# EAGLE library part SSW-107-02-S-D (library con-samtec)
THROUGH-HOLE .025" SQ POST SOCKET Source: Samtec SSW.pdf
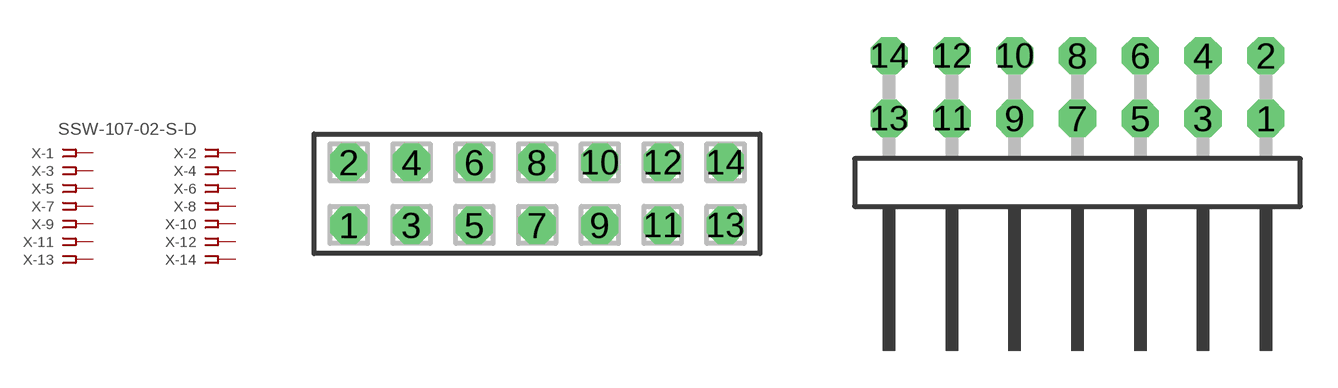
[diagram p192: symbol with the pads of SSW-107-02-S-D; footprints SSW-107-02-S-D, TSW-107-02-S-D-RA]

Designator prefix X; gates -1=FPINV -2=FPIN -3=FPIN -4=FPIN -5=FPIN -6=FPIN -7=FPIN -8=FPIN -9=FPIN -10=FPIN -11=FPIN -12=FPIN -13=FPIN -14=FPIN

## SSW-107-02-S-D (MPN: SSW-107-02-S-D; OC_FARNELL: unknown; OC_NEWARK: 11P9431)  [SSW-107-02-S-D]
1  -1:1  pas
2  -2:1  pas
3  -3:1  pas
4  -4:1  pas
5  -5:1  pas
6  -6:1  pas
7  -7:1  pas
8  -8:1  pas
9  -9:1  pas
10  -10:1  pas
11  -11:1  pas
12  -12:1  pas
13  -13:1  pas
14  -14:1  pas

## SSW-107-02-S-D-RA (MPN: SSW-107-02-S-D-RA; OC_FARNELL: unknown; OC_NEWARK: 11P9432)  [TSW-107-02-S-D-RA]
Pads as for SSW-107-02-S-D

## Footprint SSW-107-02-S-D (pad centres in mm)
THROUGH-HOLE .025" SQ POST SOCKET Source: Samtec SSW.pdf
drill 1 pad 1.5 octagon: 1 -7.62,-1.27; 2 -7.62,1.27; 3 -5.08,-1.27; 4 -5.08,1.27; 5 -2.54,-1.27; 6 -2.54,1.27; 7 0,-1.27; 8 0,1.27; 9 2.54,-1.27; 10 2.54,1.27; 11 5.08,-1.27; 12 5.08,1.27; 13 7.62,-1.27; 14 7.62,1.27

## Footprint TSW-107-02-S-D-RA (pad centres in mm)
THROUGH-HOLE .025" SQ POST HEADER Source: Samtec TSW.pdf
drill 1 pad 1.5 octagon: 1 7.62,1.524; 2 7.62,4.064; 3 5.08,1.524; 4 5.08,4.064; 5 2.54,1.524; 6 2.54,4.064; 7 0,1.524; 8 0,4.064; 9 -2.54,1.524; 10 -2.54,4.064; 11 -5.08,1.524; 12 -5.08,4.064; 13 -7.62,1.524; 14 -7.62,4.064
